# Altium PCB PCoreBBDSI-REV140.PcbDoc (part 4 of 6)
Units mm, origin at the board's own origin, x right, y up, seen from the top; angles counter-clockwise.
Board outline 100 x 72 mm, 6 copper layers (Top Layer, Int1 (GND), Int2 (Sign), Int3 (Sign), Int4 (GND), Bottom Layer), stack 1.551 mm thick; 358 components, 403 nets, 1535 pads, 844 vias.
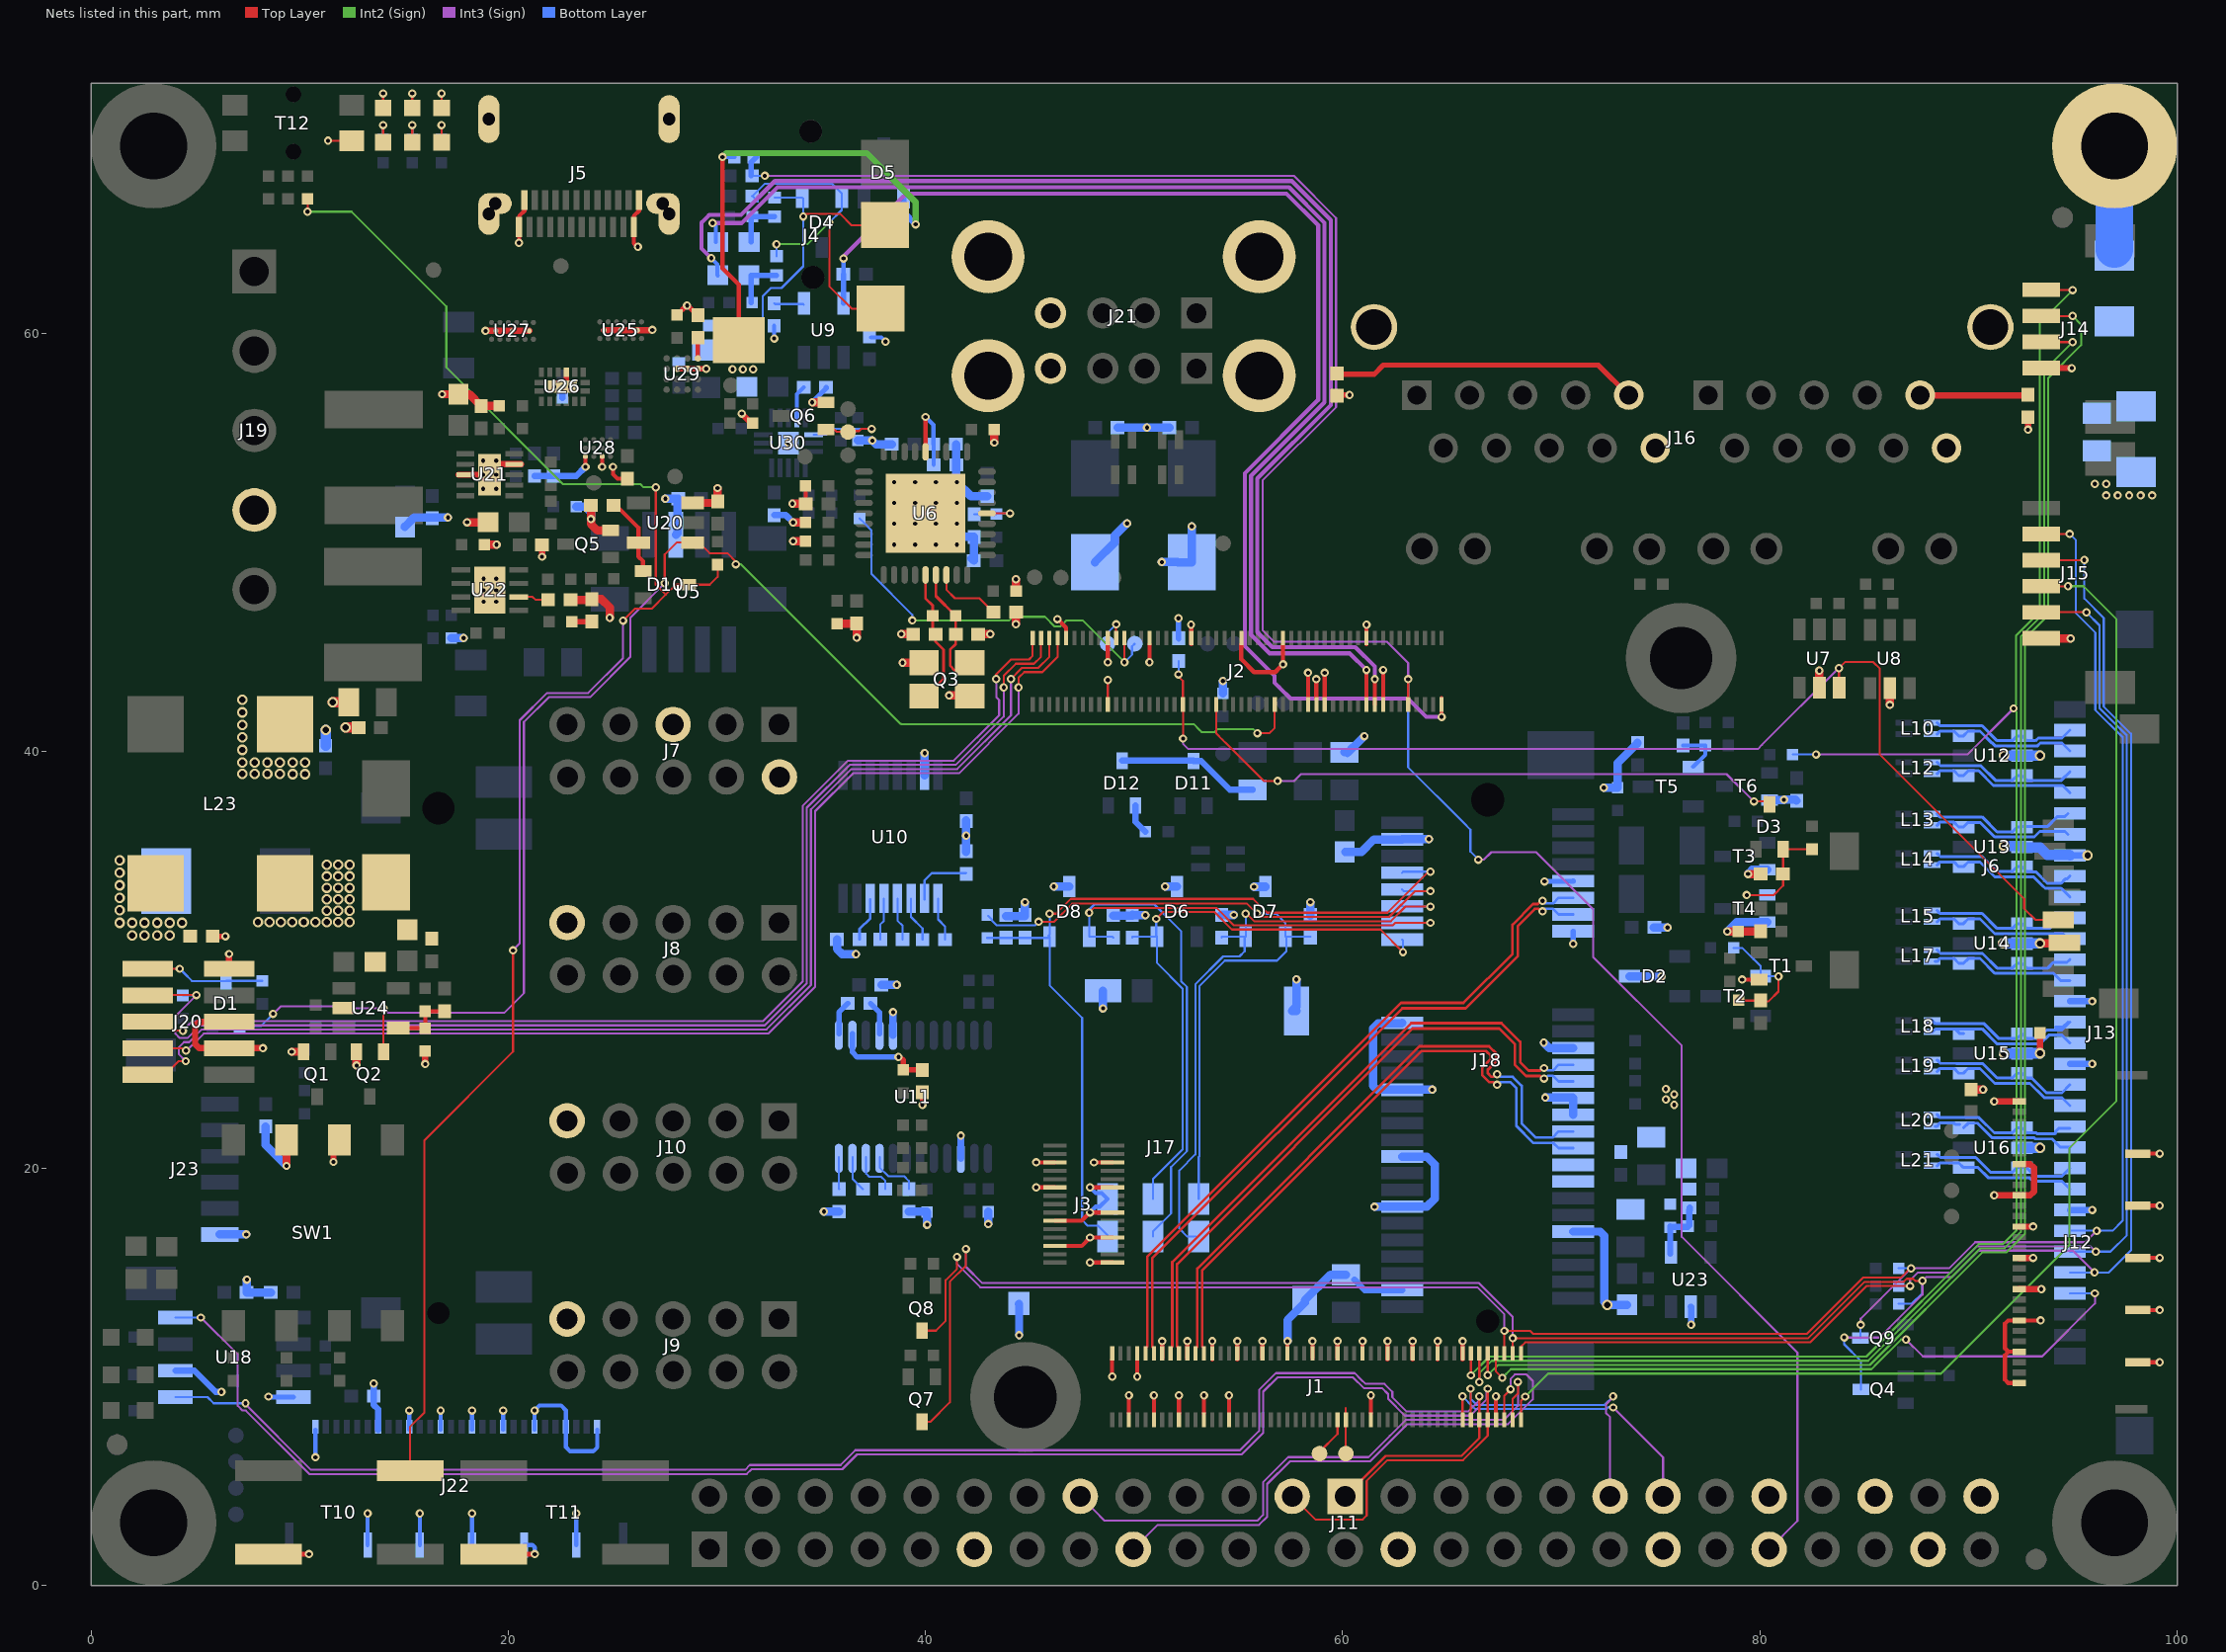
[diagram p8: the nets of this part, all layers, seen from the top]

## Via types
v1: diameter 0.4, hole 0.2, Top Layer to Bottom Layer, tented both sides, 716 vias
v2: diameter 0.5, hole 0.3, Top Layer to Bottom Layer, tented both sides, 102 vias
v3: diameter 0.4, hole 0.2, Top Layer to Bottom Layer, tented bottom, 16 vias
v4: diameter 0.9, hole 0.9, Top Layer to Bottom Layer, 6 vias
v5: diameter 0.5, hole 0.5, Top Layer to Bottom Layer, 2 vias
v6: diameter 3.2, hole 3.2, Top Layer to Bottom Layer, tented both sides, 2 vias

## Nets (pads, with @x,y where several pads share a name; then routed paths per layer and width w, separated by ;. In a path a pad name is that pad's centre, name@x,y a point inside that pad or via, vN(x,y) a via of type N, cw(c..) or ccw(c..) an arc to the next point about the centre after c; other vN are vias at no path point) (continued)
GND: C2.2 C3.1 C4.2 C5.2 C6.1 C7.1 C8.2 C9.1 C10.1 C11.1 C12.1 C13.1 C14.1 C15.1 C16.1 C17.1 C18.1 C19.1 C20.1 C22.1 C23.1 C25.1 C31.1 C32.1 C34.2 C35.2 C37.2 C39.2 C41.2 C42.2 C43.2 C45.1 C46.1 C47.1 C49.1 C50.2 C53.1 C54.1 C55.1 C56.1 C57.1 C58.1 C59.1 C60.1 C61.1 C62.1 C63.1 C64.1 C65.1 C66.1 C69.1 C70.1 C71.1 C72.2 C74.1 C75.1 C76.1 C77.1 C78.1 C79.1 C80.1 C81.1 C82.1 C83.1 C84.1 C86.1 C87.1 C88.1 C90.1 C91.1 C92.1 C97.1 C98.1 C99.1 C100.1 C101.1 C102.2 C103.1 C104.1 C105.1 C106.1 D2.3 D6.3 D7.3 D8.3 D13.1 D14.1 D15.1 J1.8 J1.15 J1.21 J1.27 J1.33 J1.38 J1.39 J1.45 J1.51 J1.57 J1.63 J1.69 J1.72 J1.75 J1.78 J1.81 J1.84 J1.87 J1.90 J1.93 J1.96 J1.99 J2.16 J2.19 J2.30 J2.32 J2.34 J2.39 J2.49 J2.61 J2.71 J2.81 J2.82 J2.91 J3.2 J3.5 J3.8 J3.11 J3.14 J3.19 J3.20 J3.25 J3.26 J5.A1 J5.A12 J5.B1 J5.B12 J6.6 J7.2 J7.5 J8.9 J9.9 J10.9 J11.11 J11.27 J11.37 J11.42 J11.46 J11.47 J11.50 J12.1 J12.4 J12.7 J12.10 J12.13 J12.16 J12.19 J12.22 J12.28 J12.29 J12.30 J12.31 J12.32 J12.33 J13.7 J13.14 J13.17 J13.24 J14.4 J15.6 J16.L10 J16.R10 J17.C5 J17.HD1 J17.HD2DSW1 J17.HD3 J17.HD4 J18.4 J18.9 J18.15 J18.18 J18.21 J18.26 J18.27 J18.29 J18.34 J18.35 J18.37 J18.40 J18.43 J18.50 J20.3 J20.5 J20.9 J21.A4 J21.B4 J22.1 J22.4 J22.7 J22.10 J22.13 J22.16 J22.19 J22.22 J22.28 J22.29 J22.30 J22.31 J22.32 J22.33 J23.6 L23.3 Q1.2 Q2.2 Q3.2 Q3.4 Q5.2 Q6.2 R1.2 R13.1 R14.1 R15.1 R16.1 R17.1 R18.1 R19.1 R22.2 R25.1 R32.1 R36.1 R38.1 R49.1 R60.1 R67.1 R74.1 R77.1 R85.1 R88.1 R90.1 R91.1 R94.2 R96.1 SW1.6 SW1.7 T1.2 T3.2 T4.2 T6.2 T10.3 T11.3 T12.3 U5.6 U6.37 U7.2 U8.2 U10.15 U11.5 U11.15 U12.2 U13.2 U14.2 U15.2 U16.2 U18.2 U18.8 U20.3 U21.3 U21.9 U21.11 U22.9 U23.2 U24.2 U25.B1 U25.B2 U25.B3 U26.11 U26.17 U27.B1 U27.B2 U27.B3 U28.B3 U28.D3 U29.B3 U29.C3 U29.D3 U30.17 | length 282.8
  Top Layer w0.1: v1(11.36,69.25) T12.3@12.5,69.25 ; D15.1@14,70.75 D15.1@14,70.825 v1@14,71.45 ; D13.1@15.4,70.75 D13.1@15.4,70.825 v1@15.4,71.45 ; D14.1@16.8,70.75 D14.1@16.8,70.825 v1@16.8,71.45 ; J2.82@48.738,42.519 v1@48.738,43.398
  Top Layer w0.2: v1(20.51,64.36) 20.52,64.37 20.52,65.64 20.77,65.89 J5.B1@20.77,66.415 ; v1@23.7,53.732 U28.D3@23.7,54.12 ; v1@24.5,53.726 U28.B3@24.5,54.12 ; v1(25.02,53.62) 25.02,53.27 25.24,53.05 C101.1@25.71,53.05 ; v1(26.21,64.17) 26.184,64.17 26.02,64.334 J5.A1@26.02,65.115 26.02,65.64 26.27,65.89 J5.B12@26.27,66.415 ; R17.1@34.25,50.05 R17.1@34.3,50.05 ; R15.1@34.25,52.7 34.26,52.69 C13.1@34.26,51.85 ; R18.1@35.76,46.1 R18.1@35.77,46.11 ; v1(45.31,19.08) 45.314,19.076 J3.19@46.209,19.076 ; v1(45.31,20.28) 45.314,20.276 J3.25@46.209,20.276 ; J3.5@46.209,16.276 47.49,16.276 v1(47.89,16.676) J3.8@48.959,16.676 ; J3.11@46.209,17.476 47.486,17.476 v1(47.89,17.88) 47.894,17.876 J3.14@48.959,17.876 ; v1(46.33,46.32) 46.74,45.91 J2.91@46.74,45.41 ; v1(47.89,19.076) J3.20@48.959,19.076 ; v1@48.074,15.476 J3.2@48.959,15.476 ; v1(48.074,20.276) J3.26@48.959,20.276 ; v1@48.738,43.398 v1(48.74,43.4) ; v1(48.74,44.25) J2.81@48.74,45.19 ; J1.99@48.948,10.839 48.948,9.962 48.95,9.964 v1(48.95,10.01) ; J1.96@49.748,8.229 49.748,9.108 v1(49.75,9.11) ; J1.93@50.148,10.839 50.148,9.962 50.15,9.964 v1(50.15,10.01) ; J2.71@50.738,45.129 50.738,44.252 v1(50.74,44.25) ; J1.90@50.948,8.229 50.948,9.108 v1(50.95,9.11) ; J1.87@51.35,10.9 J1.87@51.35,11.12 v1@51.35,11.71 ; J1.84@52.148,8.229 52.148,9.108 v1(52.15,9.11) ; J1.81@52.55,10.9 J1.81@52.55,11.12 v1(52.55,11.71) ; J2.61@52.738,45.129 v1@52.738,46.05 ; J1.78@53.348,8.229 53.35,8.231 v1(53.35,9.11) ; J1.75@53.748,10.839 53.748,11.712 v1(53.75,11.71) ; J1.72@54.548,8.229 54.55,8.231 v1(54.55,9.11) ; J1.69@54.948,10.839 54.948,11.712 v1(54.95,11.71) ; J2.49@55.138,45.129 55.138,44.392 55.75,43.78 56.768,43.78 56.96,43.972 v1(57.138,44.15) J2.39@57.138,45.129 ; J1.63@56.15,10.9 J1.63@56.15,11.12 v1(56.15,11.71) ; J1.57@57.35,10.9 J1.57@57.35,11.12 v1(57.35,11.71) ; J2.34@58.338,42.519 58.338,42.791 ; 58.34,42.791 v1(58.34,43.75) ; J1.51@58.55,10.9 J1.51@58.55,11.12 v1(58.55,11.71) ; J2.32@58.738,42.519 v1(58.738,43.44) ; J2.30@59.138,42.519 v1(59.138,43.75) ; J1.45@59.75,10.9 J1.45@59.75,11.12 v1(59.75,11.71) ; J1.39@60.95,10.9 v1(60.95,11.71) ; J2.19@61.138,45.129 61.138,46.048 v1(61.14,46.05) ; J1.38@61.348,8.229 61.348,9.108 v1(61.35,9.11) ; v1(61.938,43.88) 61.938,43.608 61.94,43.606 61.94,43.274 61.938,43.272 61.938,42.971 61.94,42.97 61.94,42.791 J2.16@61.94,42.23 ; J1.33@62.148,10.839 62.148,11.712 v1(62.15,11.71) ; J1.27@63.348,10.839 63.348,11.12 63.348,11.712 v1(63.35,11.71) ; J1.21@64.548,10.839 64.548,11.712 v1(64.55,11.71) ; J1.15@65.748,10.839 65.748,11.71 65.748,11.712 v1(65.75,11.71) ; J1.8@67.348,8.229 v1(67.348,9.063) v1@67.348,9.1 ; v1(79.15,29.04) T1.2@79.955,29.04 ; J12.1@92.435,9.7 91.9,9.7 91.75,9.85 91.75,11.04 91.91,11.2 ; J12.4@92.435,11.2 91.91,11.2 ; v1(93.46,12.7) J12.7@92.435,12.7 91.9,12.7 91.75,12.55 91.75,11.36 91.91,11.2 ; J12.29@98.11,10.7 v1(99.165,10.7) ; J12.30@98.11,13.2 v1(99.165,13.2) ; J12.31@98.11,15.7 v1(99.165,15.7) ; J12.32@98.11,18.2 v1(99.165,18.2) ; J12.33@98.11,20.7 v1(99.165,20.7)
  Top Layer w0.25: U26.11@22.79,58.16 22.79,57.66 22.98,57.47 v1(22.98,57.46) ; U29.B3@28.09,58.32 U29.C3@28.59,58.32 U29.D3@29.09,58.32 v1(29.49,58.32)
  Top Layer w0.254: C70.1@5.83,31.12 5.84,31.11 v1@6.44,31.11 ; T10.3@8.5,1.5 v1(10.45,1.5) ; T11.3@19.3,1.5 v1(21.27,1.5) ; R91.1@28.09,60.9 28.545,61.355 v1(28.57,61.355) ; v1@28.57,61.35 28.6,61.35 29.06,60.89 C102.2@29.09,60.89 ; v1(39.85,23.04) C41.2@39.85,23.63 ; Q3.4@42.121,42.634 Q3.4@42.125,42.63 ; C54.1@59.73,57.06 v1(60.33,57.06)
  Top Layer w0.3: v1(91.23,18.7) J12.19@92.435,18.7 92.96,18.7 93.14,18.88 93.14,20.02 92.96,20.2 J12.22@92.435,20.2 ; v1(91.23,23.2) J12.28@92.435,23.2 ; J12.10@92.435,14.2 93.027,14.2 v1(93.49,14.2) ; J12.13@92.435,15.7 92.74,15.7 v1(93.09,15.7) ; J12.16@92.435,17.2 92.74,17.2 v1(93.09,17.2) ; R25.1@93.42,26.48 93.425,26.475 93.425,25.515 v2(93.43,25.51)
  Top Layer w0.305: J20.5@6.62,27.02 5.17,27.02 4.99,26.84 4.99,25.95 5.19,25.75 J20.3@6.62,25.75 v1(8.24,25.75) ; J20.9@6.62,29.56 v1(6.62,30.27) ; v1(11.62,20.3) 11.62,21.06 SW1.6@11.91,21.35 ; v1(16.02,24.99) R88.1@16.02,25.61 ; U21.3@17.615,53.24 U21.3@17.94,53.24 v1(18.8,53.24) U21.11@19.11,53.24 19.61,53.74 U21.9@20.28,53.74 U21.9@20.605,53.74 ; v1(18.91,60.137) U27.B1@19.402,60.137 U27.B2@20.202,60.137 U27.B3@21.002,60.137 ; v1(21.62,49.31) C80.1@21.62,49.88 C80.1@21.642,49.88 ; U25.B1@24.59,60.17 U25.B2@25.39,60.17 U25.B3@26.19,60.17 26.9,60.17 v1(26.91,60.18) ; v1(31.19,56.17) 31.645,55.715 R90.1@31.72,55.715 ; U7.2@82.85,43.03 U7.2@82.865,43.045 ; v1(92.85,55.4) C53.1@92.85,56 C53.1@92.85,56.04 ; J14.4@93.59,58.355 94.945,58.355 v1(94.95,58.35) ; v1@94.885,45.395 v1(94.89,45.39)
  Top Layer w0.35: C83.1@12.36,42.33 C83.1@12.59,42.33
  Top Layer w0.4: v1(9.37,20.11) SW1.7@9.37,21.35 ; v1(9.62,25.58) 10.06,25.58 10.19,25.45 Q1.2@10.19,25.575 ; Q2.2@12.72,25.46 Q2.2@12.72,25.585 12.72,24.98 12.73,24.97 v1(12.73,24.92) ; v1(16.83,57.1) C75.1@17.614,57.1 18.144,57.1 C76.1@18.704,56.54 R67.1@19.574,56.54 ; v1(18.03,50.96) C79.1@18.93,50.96 ; R74.1@18.86,49.89 v1(19.44,49.89) ; C81.1@22.99,47.24 C84.1@24.01,47.24 ; C74.1@23.96,51.78 v1(23.96,51.11) 23.96,50.88 24.27,50.57 Q5.2@24.905,50.57 ; C84.1@24.01,47.28 24.47,47.28 24.86,46.89 v1(24.86,46.38) ; U20.3@28.84,51.89 29.96,51.89 C69.1@30.04,51.97 30.01,52 30.03,52.02 v1(30.03,52.6) ; v1(33.62,51.85) C13.1@34.26,51.85 ; v1(33.66,50.05) R17.1@34.25,50.05 ; v1(33.66,50.95) R16.1@34.25,50.95 ; v1(34.57,56.71) Q6.2@35.225,56.71 ; R18.1@35.77,46.11 C10.1@36.7,46.11 v1(36.7,45.43) ; v1(38.84,45.6) C18.1@39.41,45.6 ; v1(38.901,44.234) Q3.2@39.921,44.234 ; v1(41.13,42.66) 42.095,42.66 Q3.4@42.121,42.634 ; C17.1@42.55,45.58 C17.1@42.53,45.6 v1(43.1,45.6) ; v1(43.3,54.78) R14.1@43.3,55.41 ; C16.1@44.266,46.576 C16.1@44.34,46.65 ; v1@44.34,46.11 C16.1@44.34,46.65 ; v1(44.34,48.23) 44.34,47.68 R13.1@44.35,47.67 ; C16.1@44.35,46.64 C16.1@44.34,46.65 ; v1(78.44,31.35) R19.1@78.96,31.35 80.02,31.35 C19.1@80.03,31.36 ; v1(79.43,34.1) C25.1@80.03,34.1 ; U7.2@82.85,43.03 v1(82.85,43.85) ; v1(86.231,42.209) U8.2@86.23,43.01 ; C46.1@90.12,23.77 v1(90.695,23.77) ; v2@93.43,30.78 94.58,30.78 J6.6@94.6,30.8 ; J15.6@93.59,45.395 v1@94.885,45.395
  Top Layer w0.406: v1(18.82,47.7) 18.83,47.71 U22.9@19.11,47.71 ; U6.37@40,51.39 U6.37@40,51.4
  Top Layer w0.5: v2(11.59,42.33) C83.1@12.36,42.33 ; v2(12.2,41.12) C82.1@12.82,41.12
  Int3 (Sign) w0.1: v1(61.35,9.11) v1@61.45,9.01
  Bottom Layer w0.2: v1(10.76,6.14) J22.28@10.76,7.46 ; v1@13.25,3.45 13.26,3.44 J22.33@13.26,1.935 ; J22.19@15.26,7.46 J22.19@15.26,7.61 v1(15.26,8.385) ; J22.32@15.76,1.935 v1@15.76,3.44 ; J22.16@16.76,7.46 J22.16@16.76,7.61 v1(16.76,8.385) ; J22.31@18.26,1.935 v1@18.26,3.44 ; J22.13@18.26,7.46 J22.13@18.26,7.61 v1(18.26,8.385) ; J22.10@19.76,7.46 v1(19.76,8.385) ; J22.30@20.76,1.935 21.155,1.935 21.27,1.82 v1(21.27,1.5) ; J22.7@21.26,7.46 v1@21.26,8.33 ; v1(21.26,8.385) 21.495,8.62 22.53,8.62 22.76,8.39 J22.4@22.76,7.61 22.76,6.63 22.96,6.43 24.07,6.43 24.26,6.62 J22.1@24.26,7.46 ; J22.29@23.26,1.935 v1@23.26,3.44 ; v1(32.75,59.77) C32.1@32.75,60.38 ; C31.1@37.4,59.82 37.88,59.82 v1(38.08,59.62) ; v1(47.89,17.88) 48.164,18.154 48.354,18.154 J17.C5@48.72,18.52 48.438,18.802 48.164,18.802 v1(47.89,19.076) ; v1@57.113,44.125 v1(57.138,44.15) ; C64.1@60.225,39.805 60.51,40.09 60.51,40.185 C64.1@60.51,40.31
  Bottom Layer w0.25: v1(34.57,56.71) 35.24,57.38 C103.1@35.24,57.43
  Bottom Layer w0.254: v1(8.51,9.052) 8.537,9.025 U18.8@9.695,9.025 ; v1(52.13,46.36) C20.1@52.13,45.4 52.13,45.375 C20.1@52.137,45.367 ; v1(69.676,33.746) 69.683,33.753 71.043,33.753 J18.9@71.05,33.76 ; v1(71.05,30.75) J18.15@71.05,31.36
  Bottom Layer w0.3: v1(13.55,9.68) C106.1@13.55,9.07 13.55,8.65 13.76,8.44 J22.22@13.76,7.61 J22.22@13.76,7.46
  Bottom Layer w0.305: U18.2@4.045,10.295 4.955,10.295 5.97,9.28 v1(6.25,9.28) ; C98.1@21.26,53.18 C97.1@22.17,53.18 23.26,53.18 v1(23.7,53.62) ; v1(22.2,57.46) 22.48,57.46 22.59,57.35 R96.1@22.59,56.92 ; C105.1@32.75,51.3 33.31,51.3 v1(33.66,50.95) ; C63.1@60.552,14.66 61.052,14.16 J18.50@62.85,14.16 ; U23.2@76.68,13.36 76.7,13.34 v1(76.7,12.5) ; J13.24@94.86,18 v1(95.93,18) ; J13.17@94.86,25 v1(95.93,25) ; J13.14@94.86,28 v1(95.93,28) ; J13.7@94.86,35 v2(95.71,35)
  Bottom Layer w0.35: U11.5@38.445,26.37 v1(38.445,27.48) ; U11.15@41.695,20.47 v1(41.695,21.56)
  Bottom Layer w0.4: J23.6@6.17,16.825 7.435,16.825 v1(7.44,16.82) ; v1(7.47,14.66) 7.46,14.65 C50.2@7.46,14.04 C49.1@8.62,14.04 ; C47.1@8.37,22 8.37,21.11 v1(9.37,20.11) ; C77.1@15.05,50.73 15.05,50.755 15.485,51.19 v1(17.11,51.19) ; R77.1@17.27,45.41 v1(17.86,45.41) ; R60.1@23.26,51.71 23.7,51.71 23.96,51.45 v1(23.96,51.11) ; v1(27.53,52.09) C3.1@28.15,52.09 28.15,52.04 28.118,52.008 28.118,51.333 U5.6@28.15,51.3 ; U5.6@28.035,50.36 28.118,50.443 U5.6@28.118,51.3 ; v1(35.13,17.92) C42.2@35.86,17.92 ; C37.2@35.76,30.97 35.76,30.51 36.01,30.26 v1(36.67,30.26) ; R94.2@36.75,54.88 v1(37.45,54.88) 37.63,54.7 C12.1@38.39,54.7 ; C39.2@37.89,28.79 v1(38.62,28.79) ; C43.2@39.2,17.92 40.06,17.92 R38.1@40.08,17.9 v1(40.08,17.29) ; U10.15@39.955,38.83 39.96,38.835 v1(39.96,39.9) ; C14.1@41.46,54.7 41.465,54.695 C15.1@41.465,53.729 ; C15.1@41.473,53.721 41.465,53.713 41.465,52.925 v3(41.5,52.89) 42.18,52.21 C11.1@42.96,52.21 ; v3(41.5,50.89) 41.5,50.65 41.89,50.26 C8.2@42.33,50.26 42.33,49.13 C9.1@42.32,49.12 C9.1@42.21,49.23 ; C35.2@41.95,35.15 C35.2@41.95,35.19 v1(41.95,35.94) C34.2@41.95,36.64 C34.2@41.95,36.68 ; v1(43.01,17.32) R36.1@43.01,17.91 ; J17.HD4@44.48,13.5 44.49,13.49 v1(44.49,11.99) ; C4.2@48.12,49.04 49.07,49.99 49.07,50.32 v1(49.66,50.91) ; C6.1@49.21,55.5 v1(50.62,55.5) C7.1@51.69,55.5 ; v1(51.33,49.05) 52.084,49.05 52.094,49.04 C5.2@52.764,49.04 52.77,49.046 v1(52.77,50.77) ; R22.2@54.26,42.76 v1(54.26,43.35) ; v1(57.35,11.71) 57.35,12.72 58.18,13.55 J17.HD1@58.18,13.66 59.41,14.89 C63.1@60.16,14.89 ; C64.1@60.09,39.94 60.265,39.94 60.51,40.185 60.565,40.24 v1@61.035,40.71 ; C65.1@60.12,35.16 60.9,35.16 61.5,35.76 J18.4@62.85,35.76 62.86,35.77 v1(64.13,35.77) ; v1(61.53,18.15) 61.536,18.156 62.847,18.156 J18.40@62.85,18.16 64.04,18.16 64.41,18.53 64.41,20.18 64.034,20.556 62.854,20.556 J18.34@62.85,20.56 ; J18.18@62.85,26.96 62.84,26.95 61.7,26.95 61.45,26.7 61.45,23.95 61.64,23.76 J18.26@62.85,23.76 v1(64.29,23.76) ; v1(69.64,26.02) 69.9,25.76 J18.21@71.05,25.76 ; v1(69.71,23.38) 71.03,23.38 J18.27@71.05,23.36 J18.29@71.05,22.56 ; J18.43@71.05,16.96 72.34,16.96 72.55,16.75 72.55,13.58 v2(72.68,13.45) C88.1@73.63,13.45 ; v1(72.52,38.24) R49.1@73.17,38.24 73.17,39.414 74.016,40.26 74.02,40.26 74.13,40.37 C23.1@74.13,40.39 ; D2.3@73.75,29.2 v1(75.28,29.2) ; C45.1@74.9,31.54 C45.1@74.94,31.54 v1(75.57,31.54) ; v1(78.44,31.35) 78.88,31.79 T4.2@80.355,31.79 ; v1(79.43,34.1) 79.63,34.3 T3.2@80.355,34.3 ; T6.2@80.455,37.65 81.14,37.65 v1(81.15,37.66) 81.71,37.66 C22.1@81.76,37.61
  Bottom Layer w0.406: C60.1@43.86,32.09 44.77,32.09 C59.1@44.77,32.13 v1(44.77,32.75) ; v1(46.15,33.5) D8.3@46.9,33.5 ; v1(48.51,27.66) J17.HD3@48.51,28.51 ; C56.1@49,32.1 49.92,32.1 C55.1@49.92,32.14 49.93,32.13 v1(50.54,32.13) ; v1(51.49,33.5) D6.3@52.05,33.5 ; C57.1@54.2,32.1 C57.1@54.2,32.14 v1(54.78,32.14) ; v1(55.75,33.49) 56.29,33.49 D7.3@56.3,33.5 ; J17.HD2DSW1@57.78,27.535 57.569,27.535 57.78,27.746 v1(57.78,29.05) ; C58.1@58.45,32.1 C58.1@58.45,32.14 v1(58.45,32.75)
  Bottom Layer w0.5: C71.1@11.25,40.25 v2(11.25,41.002) ; v2(91.658,30.77) U14.2@92.56,30.77 v2(93.43,30.77) ; v2(91.69,25.5) U15.2@92.56,25.5 92.57,25.51 v2(93.43,25.51) ; v2(91.69,35.452) 91.692,35.45 92.51,35.45 U13.2@92.56,35.4 92.583,35.377 93.423,35.377 93.775,35.025 94.835,35.025 J13.7@94.86,35 ; v2(91.69,39.77) U12.2@92.56,39.77 92.563,39.773 v2(93.433,39.773) ; U16.2@92.56,20.98 v2(93.42,20.98)
  other v1: 13.26,3.45 15.76,3.45 18.26,3.45 23.26,3.45 51.35,11.71 47.89,15.476 75.89,23.04 75.49,23.29 75.89,23.54 75.49,23.79 6.44,31.12 61.04,40.71 52.73,46.05 44.34,46.08 18.82,47.15 19.42,47.15 19.42,47.7 18.82,48.25 19.42,48.25 96.6,52.25 97.15,52.25 97.7,52.25 98.25,52.25 98.8,52.25 18.8,52.56 19.42,52.56 96.05,52.8 96.6,52.8 19.42,53.24 24.5,53.62 18.8,53.92 19.42,53.92 33.43,54.76 30.75,58.3 31.25,58.3 31.74,58.3 14,71.52 15.4,71.52 16.8,71.52
  other v2: 8,31.79 8.55,31.79 9.099,31.79 9.649,31.79 10.199,31.79 10.75,31.79 11.3,31.79 11.85,31.79 12.4,31.79 11.3,32.34 11.85,32.34 12.4,32.34 11.3,32.89 11.85,32.89 12.4,32.89 11.3,33.44 11.85,33.44 12.4,33.44 11.3,33.99 11.85,33.99 12.4,33.99 11.3,34.54 11.85,34.54 12.4,34.54
  other v3: 38.5,49.89 39.5,49.89 40.5,49.89 41.5,49.89 38.5,50.89 39.5,50.89 40.5,50.89 38.5,51.89 39.5,51.89 40.5,51.89 41.5,51.89 38.5,52.89 39.5,52.89 40.5,52.89
GND_SHIELD: C1.1 C2.1 J5.SH1 J5.SH2 J5.SH3 J5.SH4 J16.L15 J16.R15 J21.9 J21.10 J21.11 J21.12 R1.1
GNDIN: J19.4 L23.4
  other v2: 9.665,38.89 10.265,38.89 7.25,38.9 7.85,38.9 8.45,38.9 9.05,38.9 7.25,39.45 7.85,39.45 8.45,39.45 9.05,39.45 9.665,39.44 10.265,39.44 7.25,40.05 7.25,40.65 7.25,41.25 7.25,41.85 7.25,42.45
GPIO_J1_44: J1.44 TP30.1 | length 2.2
  Top Layer w0.1: TP30.1@60.15,6.32 J1.44@60.15,7.94 60.15,8.231 60.15,8.501
GPIO_J1_46: J1.46 TP31.1 | length 2
  Top Layer w0.1: TP31.1@58.89,6.32 58.89,6.4 59.75,7.26 J1.46@59.75,7.94
I2C_B_SCL: J1.3 J13.27 J15.3 Q4.3 Q7.3 R8.2 | length 118.7
  Top Layer w0.1: Q7.3@39.83,7.845 40.235,7.845 41.17,8.78 41.17,14.55 41.934,15.314 v1(41.934,16.13) ; J1.3@68.15,11.12 68.15,11.73 68.27,11.85 82.317,11.85 85.017,14.55 86.89,14.55 87.04,14.7 87.345,14.7 87.445,14.6 v1(87.79,14.6) ; J15.3@93.595,49.15 v1(95.55,49.15)
  Int3 (Sign) w0.1: v1(41.934,16.13) 41.934,15.276 42.72,14.49 66.537,14.49 68.15,12.877 v1(68.15,11.85) ; v1(84.04,11.89) 84.047,11.883 85.738,11.883 86.21,12.355 86.21,12.36 87.79,13.94 v1(87.79,14.6) 87.98,14.79 89.223,14.79 90.483,16.05 95,16.05 v1(96.04,15.01)
  Bottom Layer w0.1: v1(84.04,11.89) 84.04,11.56 84.835,10.765 Q4.3@84.835,9.39 ; R8.2@86.65,13.5 87.28,13.5 87.79,14.01 v1(87.79,14.6) ; J13.27@94.86,15 96.04,15 96.73,15 97.79,16.06 97.79,40.82 96.48,42.13 96.48,46.37 95.55,47.3 v1(95.55,49.15)
I2C_B_SDA: J1.5 J13.25 J15.2 Q8.3 Q9.3 R9.2 | length 107.8
  Top Layer w0.1: Q8.3@39.83,12.215 40.505,12.215 40.97,12.68 40.97,14.633 41.51,15.173 v1(41.51,15.75) ; J1.5@67.75,10.841 v1(67.75,12.2) 68.005,12.2 68.295,12.2 68.99,12.2 69.14,12.05 82.234,12.05 84.934,14.75 86.75,14.75 87.2,15.2 v1(87.25,15.2) ; J15.2@93.59,50.395 93.595,50.4 v1(94.85,50.4)
  Int3 (Sign) w0.1: v1(41.51,15.75) 41.51,15.41 42.63,14.29 66.454,14.29 67.75,12.994 v1(67.75,12.2) ; v1(84.83,12.49) 84.83,12.78 v1(87.25,15.2) 89.067,15.2 90.317,16.45 95.59,16.45 v1(96.14,17)
  Bottom Layer w0.1: Q9.3@84.825,11.85 84.825,12.485 v1(84.83,12.49) ; R9.2@86.65,15.2 v1(87.25,15.2) ; v1(94.85,50.4) 95.15,50.1 95.15,46.6 96.08,45.67 96.08,41.964 97.39,40.654 97.39,17.49 96.9,17 v1(96.14,17) J13.25@94.86,17
I2S_B_RXC: J2.79 TP28.1 | length 1.8
  Top Layer w0.1: J2.79@49.14,45.41 v1(49.14,46.07)
  Bottom Layer w0.1: TP28.1@48.73,45.14 48.738,45.148 48.738,45.668 v1(49.14,46.07)
I2S_B_RXFS: J2.77 R102.2 TP27.1 | length 19.6
  Top Layer w0.1: v1@49.54,44.24 v1(49.54,44.25) J2.77@49.54,45.41
  Int2 (Sign) w0.1: v1(39.37,46.26) 44.025,46.26 44.195,46.43 45.725,46.43 46.185,45.97 46.475,45.97 46.765,46.26 47.53,46.26 v1(49.54,44.25)
  Bottom Layer w0.1: R102.2@36.84,51.15 37.065,50.925 37.41,50.58 37.41,48.491 39.37,46.531 v1(39.37,46.26) ; v1(49.54,44.25) 49.902,44.612 49.902,45.012 TP27.1@50.03,45.14
I\2\C\_\B\_\I\R\Q\: J1.1 J13.26 J15.5 R5.2 | length 66.7
  Top Layer w0.1: J1.1@68.55,10.841 68.55,11.45 68.75,11.65 82.4,11.65 85.1,14.35 v1(87.2,14.35) ; J15.5@93.59,46.645 93.595,46.65 v1(95.65,46.65)
  Int3 (Sign) w0.1: v1(87.2,14.35) 87.2,14.626 87.574,15 89.15,15 90.4,16.25 95.848,16.25 96.098,16 v1(96.1,16)
  Bottom Layer w0.1: R5.2@86.65,14.35 v1(87.2,14.35) ; J13.26@94.86,16 v1(96.1,16) 96.8,16 97.59,16.79 97.59,40.737 96.28,42.047 96.28,46.02 v1(95.65,46.65)
ILIM_5V_VBUS: Q6.1 TP8.1 U30.6 | length 5.2
  Top Layer w0.1: Q6.1@35.225,55.41 35.633,55.41 35.74,55.303 36.277,55.303 TP8.1@36.29,55.29 36.338,55.338 36.818,55.338 36.92,55.44 v1(37.42,55.44)
  Bottom Layer w0.1: U30.6@34.63,55.16 35.23,55.16 35.52,55.45 37.41,55.45 v1(37.42,55.44)
JTAG_TCK: J2.93 J20.4 | length 58
  Top Layer w0.1: J20.4@2.72,25.75 4.368,25.75 4.478,25.64 v1(4.55,25.64) ; v1(44.46,43.05) 44.46,43.51 44.73,43.78 45.6,43.78 46.338,44.518 46.338,44.849 J2.93@46.338,45.129
  Int3 (Sign) w0.1: v1(4.55,25.64) 4.59,25.64 5.4,26.45 32.463,26.45 34.71,28.697 34.71,37.111 36.531,38.932 41.606,38.932 44.46,41.786 v1(44.46,43.05)
JTAG_TDI: J2.97 J20.8 R7.1 | length 61.1
  Top Layer w0.1: J20.8@2.72,28.29 2.73,28.3 v1(5.05,28.3) ; v1(43.75,43.05) 43.75,43.305 43.75,43.6 44.33,44.18 44.53,44.18 ; 44.53,44.18 45.2,44.18 45.538,44.518 45.538,44.849 J2.97@45.538,45.129
  Int3 (Sign) w0.1: v1(5.05,28.3) 4.05,27.3 4.05,26.445 4.255,26.24 4.624,26.24 5.234,26.85 32.297,26.85 34.31,28.863 34.31,37.277 36.365,39.332 41.44,39.332 43.75,41.642 v1(43.75,43.05)
  Bottom Layer w0.1: R7.1@4.4,28.28 5.03,28.28 v1(5.05,28.3)
JTAG_TDO: J2.99 J20.6 | length 56.9
  Top Layer w0.1: J20.6@2.72,27.02 3.05,26.69 3.89,26.69 3.99,26.59 v1(4.4,26.59) ; v1@43.39,43.44 43.39,43.67 44.1,44.38 44.481,44.38 44.96,44.38 45.138,44.558 45.138,44.849 J2.99@45.138,45.129
  Int3 (Sign) w0.1: v1(4.4,26.59) 4.86,27.05 32.214,27.05 34.11,28.945 34.11,37.36 36.282,39.532 41.357,39.532 43.53,41.705 43.53,42.443 43.4,42.573 43.4,43.45 v1@43.39,43.44
  other v1: 43.39,43.45
JTAG_TMS: J2.95 J20.2 | length 58.9
  Top Layer w0.1: J20.2@2.72,24.48 3.54,24.48 4.19,25.13 v1(4.54,25.13) ; v1(44.1,43.45) 44.58,43.93 44.63,43.98 45.4,43.98 45.938,44.518 45.938,44.849 J2.95@45.938,45.129
  Int3 (Sign) w0.1: v1(4.54,25.13) 4.2,25.47 4.2,25.785 4.455,26.04 4.707,26.04 5.317,26.65 32.38,26.65 34.51,28.78 34.51,37.194 36.448,39.132 41.523,39.132 44.1,41.709 v1(44.1,43.45)
LACLK_N: J13.8 L14.3 U13.3 | length 7.3
  Bottom Layer w0.141: L14.3@88.495,35.085 88.65,34.93 89.164,34.93 90.356,34.929 ; 90.356,34.93 90.66,34.93 91.37,34.22 92.105,34.22 92.335,34.45 U13.3@92.56,34.45 92.789,34.221 93.059,34.221 93.073,34.207 93.222,34.207 93.769,33.66 94.439,33.66 94.64,33.861 94.721,33.861 J13.8@94.86,34
LACLK_P: J13.9 L14.2 U13.4 | length 7.3
  Bottom Layer w0.141: L14.2@88.495,34.535 88.574,34.614 88.574,34.638 88.62,34.683 89.302,34.683 89.535,34.45 U13.4@89.76,34.45 89.986,34.676 90.555,34.676 91.265,33.966 93.122,33.966 93.403,33.685 93.559,33.53 93.669,33.419 94.441,33.419 J13.9@94.86,33
LADATA0_N: J13.1 L10.3 U12.1 | length 7.1
  Bottom Layer w0.141: L10.3@88.495,41.355 88.574,41.276 88.574,41.252 88.62,41.206 90.654,41.206 91.37,40.49 92.105,40.49 92.335,40.72 U12.1@92.56,40.72 92.789,40.491 U12.1@93.059,40.491 ; U12.1@93.06,40.49 93.21,40.49 93.34,40.62 94.48,40.62 J13.1@94.86,41
LADATA0_P: J13.2 L10.2 U12.6 | length 7.1
  Bottom Layer w0.141: L10.2@88.495,40.805 88.574,40.884 88.574,40.908 88.62,40.953 89.302,40.953 89.535,40.72 U12.6@89.76,40.72 89.986,40.946 90.555,40.946 91.111,40.39 91.129,40.39 91.27,40.249 92.205,40.249 ; 92.205,40.249 92.96,40.249 ; 92.96,40.249 93.31,40.249 93.44,40.379 94.481,40.379 J13.2@94.86,40
LADATA1_N: J13.3 L12.3 U12.3 | length 7.1
  Bottom Layer w0.141: L12.3@88.495,39.455 88.656,39.294 89.402,39.294 89.405,39.291 90.157,39.291 90.16,39.294 90.586,39.294 91.29,38.59 92.105,38.59 92.335,38.82 U12.3@92.56,38.82 92.789,38.591 U12.3@93.059,38.591 ; U12.3@93.06,38.59 94.45,38.59 J13.3@94.86,39
LADATA1_P: J13.4 L12.2 U12.4 | length 7.1
  Bottom Layer w0.141: L12.2@88.495,38.905 88.574,38.984 88.574,39.008 88.62,39.053 89.302,39.053 89.535,38.82 U12.4@89.76,38.82 89.989,39.049 90.257,39.049 90.26,39.052 90.487,39.052 91.19,38.349 91.27,38.349 92.205,38.349 ; 92.205,38.349 92.96,38.349 93.9,38.349 94.511,38.349 J13.4@94.86,38
LADATA2_N: J13.5 L13.3 U13.1 | length 7
  Bottom Layer w0.141: L13.3@88.495,36.985 88.574,36.906 88.574,36.882 88.62,36.836 90.654,36.836 91.37,36.12 92.105,36.12 92.335,36.35 U13.1@92.56,36.35 92.6,36.39 93.8,36.39 94.271,36.861 94.621,36.861 J13.5@94.76,37
LADATA2_P: J13.6 L13.2 U13.6 | length 7
  Bottom Layer w0.141: L13.2@88.495,36.435 88.574,36.514 88.574,36.538 88.62,36.583 89.302,36.583 89.535,36.35 U13.6@89.76,36.35 89.986,36.576 90.555,36.576 91.252,35.879 93.159,35.879 93.419,36.139 94.621,36.139 J13.6@94.76,36
LADATA3_N: J13.10 L15.3 U14.1 | length 7.1
  Bottom Layer w0.141: L15.3@88.495,32.355 88.574,32.276 88.574,32.252 88.62,32.206 90.654,32.206 91.37,31.49 92.105,31.49 92.335,31.72 U14.1@92.56,31.72 92.789,31.491 U14.1@93.059,31.491 ; U14.1@93.06,31.49 93.89,31.49 94.261,31.861 94.821,31.861 J13.10@94.86,31.9
LADATA3_P: J13.11 L15.2 U14.6 | length 7.1
  Bottom Layer w0.141: L15.2@88.495,31.805 88.574,31.884 88.574,31.908 88.62,31.953 89.302,31.953 89.535,31.72 U14.6@89.76,31.72 89.986,31.946 90.555,31.946 91.261,31.24 91.964,31.24 ; 91.964,31.241 93.156,31.241 ; 93.156,31.24 94.52,31.24 J13.11@94.86,30.9
LBCLK_N: J13.20 L20.3 U16.1 | length 7.1
  Bottom Layer w0.141: L20.3@88.495,22.565 88.574,22.486 88.574,22.465 88.62,22.42 90.499,22.42 90.519,22.4 90.531,22.4 91.231,21.7 92.105,21.7 92.335,21.93 U16.1@92.56,21.93 92.79,21.7 93.247,21.7 93.305,21.642 94.135,21.642 94.181,21.687 94.181,21.771 94.31,21.9 J13.20@94.86,21.9
LBCLK_P: J13.21 L20.2 U16.6 | length 7
  Bottom Layer w0.141: L20.2@88.395,22.015 88.495,22.015 88.574,22.094 88.574,22.114 88.62,22.16 89.305,22.16 89.355,22.11 U16.6@89.58,22.11 ; U16.6@89.76,21.93 89.989,22.159 90.431,22.159 91.139,21.451 93.156,21.451 93.206,21.401 94.01,21.401 94.41,21 J13.21@94.86,21
LBDATA0_N: J13.12 L17.3 U14.3 | length 7.1
  Bottom Layer w0.141: L17.3@88.495,30.455 88.656,30.294 89.402,30.294 89.405,30.291 90.157,30.291 90.16,30.294 90.648,30.294 90.652,30.29 90.67,30.29 91.37,29.59 92.105,29.59 92.335,29.82 U14.3@92.56,29.82 92.789,29.591 U14.3@93.059,29.591 ; U14.3@93.06,29.59 93.8,29.59 94.071,29.861 94.721,29.861 J13.12@94.86,30
LBDATA0_P: J13.13 L17.2 U14.4 | length 7.2
  Bottom Layer w0.141: L17.2@88.395,29.905 88.495,29.905 88.574,29.984 88.574,30.008 88.62,30.053 89.302,30.053 89.535,29.82 U14.4@89.76,29.82 89.989,30.049 90.257,30.049 90.26,30.053 90.548,30.053 91.252,29.349 94.061,29.349 94.41,29 J13.13@94.86,29
LBDATA1_N: J13.15 L18.3 U15.1 | length 8.2
  Bottom Layer w0.141: L18.3@88.245,27.085 88.41,26.92 89.164,26.92 90.356,26.921 90.751,26.921 91.46,26.212 92.06,26.212 92.069,26.221 92.331,26.221 U15.1@92.56,26.45 92.79,26.22 93.35,26.22 93.75,26.62 94.48,26.62 J13.15@94.86,27 ; J13.15@94.179,26.771 94.531,26.771 J13.15@94.76,27
LBDATA1_P: J13.16 L18.2 U15.6 | length 7.8
  Bottom Layer w0.141: L18.2@88.245,26.535 88.275,26.535 88.413,26.673 U15.6@89.358,26.673 ; U15.6@89.76,26.45 89.588,26.45 89.358,26.679 89.537,26.679 90.651,26.679 91.36,25.971 93.441,25.971 93.449,25.979 ; 93.45,25.979 93.85,26.379 94.481,26.379 J13.16@94.86,26
LBDATA2_N: J13.18 L19.3 U15.3 | length 7.4
  Bottom Layer w0.141: L19.3@88.495,25.185 88.656,25.024 89.402,25.024 89.405,25.021 90.356,25.021 ; 90.356,25.02 90.67,25.02 91.37,24.32 92.105,24.32 92.335,24.55 U15.3@92.56,24.55 92.789,24.321 93.029,24.321 93.73,23.62 94.48,23.62 J13.18@94.86,24
LBDATA2_P: J13.19 L19.2 U15.4 | length 7.4
  Bottom Layer w0.141: L19.2@88.495,24.635 88.574,24.714 88.574,24.738 88.62,24.783 89.302,24.783 89.535,24.55 U15.4@89.76,24.55 89.986,24.776 90.555,24.776 91.265,24.066 92.943,24.066 93.589,23.42 93.63,23.379 94.481,23.379 J13.19@94.86,23
LBDATA3_N: J13.22 L21.3 U16.3 | length 7.1
  Bottom Layer w0.141: L21.3@88.495,20.665 88.65,20.51 89.164,20.51 ; 89.164,20.509 90.347,20.509 91.046,19.81 92.115,19.81 92.335,20.03 U16.3@92.56,20.03 92.78,20.03 93.19,19.62 94.48,19.62 J13.22@94.86,20
LBDATA3_P: J13.23 L21.2 U16.4 | length 7
  Bottom Layer w0.141: L21.2@88.495,20.115 88.574,20.194 88.574,20.211 88.62,20.256 89.534,20.256 U16.4@89.76,20.03 90.46,20.03 90.94,19.55 92.91,19.55 93.081,19.379 94.48,19.379 94.481,19.379 J13.23@94.86,19
MPCIE_CLK_N: J1.91 J18.11 | length 32.9
  Top Layer w0.127: J1.91@50.548,11.368 50.642,11.462 50.642,15.772 62.797,27.927 65.788,27.927 68.139,30.278 68.139,31.675 69.122,32.658 69.354,32.658 69.506,32.81 v1(69.58,32.81)
  Bottom Layer w0.127: v1(69.58,32.81) 69.7,32.69 69.918,32.69 70.08,32.69 70.35,32.96 J18.11@71.05,32.96
MPCIE_CLK_P: J1.89 J18.13 | length 32.5
  Top Layer w0.127: J1.89@50.948,11.372 50.87,11.45 50.87,15.677 62.859,27.666 65.896,27.666 68.4,30.17 68.4,31.613 69.217,32.43 69.386,32.43 69.506,32.31 v1(69.58,32.31)
  Bottom Layer w0.127: v1(69.58,32.31) 69.7,32.43 69.81,32.43 70.08,32.43 70.35,32.16 J18.13@71.05,32.16
MPCIE_CRX_N: J1.85 J18.23 | length 29.9
  Top Layer w0.127: J1.85@51.748,11.368 51.832,11.452 51.832,15.502 63.287,26.957 67.608,26.957 68.507,26.057 68.507,25.077 68.904,24.68 69.473,24.68 69.592,24.8 v1(69.65,24.8)
  Bottom Layer w0.127: v1(69.65,24.8) 69.718,24.8 69.828,24.69 70.08,24.69 70.35,24.96 J18.23@71.05,24.96
MPCIE_CRX_P: J1.83 J18.25 | length 29.5
  Top Layer w0.127: J1.83@52.148,11.372 52.06,11.46 52.06,15.407 63.349,26.696 67.5,26.696 68.247,25.95 68.247,24.969 68.796,24.42 69.473,24.42 69.592,24.3 v1(69.65,24.3)
  Bottom Layer w0.127: v1(69.65,24.3) 69.708,24.3 69.838,24.43 70.08,24.43 70.35,24.16 J18.25@71.05,24.16
MPCIE_CTX_N: J1.79 J18.31 | length 31
  Top Layer w0.127: J1.79@52.948,10.839 52.948,11.368 53.03,11.45 53.03,15.19 63.68,25.84 67.02,25.84 67.363,25.497 67.363,25.129 66.95,24.716 66.95,24.569 67.138,24.38 67.222,24.38 67.342,24.5 v1(67.4,24.5)
  Bottom Layer w0.127: v1(67.4,24.5) 67.458,24.5 67.577,24.38 68.154,24.38 68.58,23.954 68.58,22.148 69.259,21.47 70.06,21.47 70.35,21.76 J18.31@71.05,21.76
MPCIE_CTX_P: J1.77 J18.33 | length 30.1
  Top Layer w0.127: J1.77@53.348,11.372 53.258,11.462 53.258,15.095 63.775,25.612 66.88,25.612 67.103,25.389 67.103,25.237 66.704,24.838 66.689,24.824 66.689,24.461 66.704,24.446 67.03,24.12 67.222,24.12 67.342,24 v1(67.4,24)
  Bottom Layer w0.127: v1(67.4,24) 67.458,24 67.577,24.12 68.046,24.12 68.32,23.846 68.32,22.04 69.151,21.209 70.101,21.209 70.35,20.96 J18.33@71.05,20.96
NetC1_2: C1.2 U4.1 | length 4.9
  Bottom Layer w1.778: C1.2@96.99,64.06 96.99,68.99 U4.1@97,69
NetC8_1: C8.1 R11.2 U6.5 | length 3
  Top Layer w0.1: U6.5@42.95,51.39 43.84,51.39 ; v1(44.05,51.39) 43.84,51.39 ; 43.84,51.39 43.78,51.39 43.84,51.39
  Bottom Layer w0.1: C8.1@42.33,51.34 43.14,51.34 43.39,51.34 43.44,51.39 v1(44.05,51.39)
NetC14_2: C14.2 C15.2 U6.14 | length 4.1
  Top Layer w0.2: U6.14@40,54.39 v1(40,56.01)
  Bottom Layer w0.2: v1(40,56.01) 40.216,55.794 40.38,55.63 C14.2@40.38,54.7 40.393,54.687 C15.2@40.393,53.721
NetC16_2: C16.2 U6.34 | length 3.4
  Top Layer w0.1: U6.34@41,48.39 41,47.73 41.41,47.32 42.59,47.32 C16.2@43.26,46.65
NetC17_2: C17.2 Q3.1 R12.1 U6.33 | length 6.1
  Top Layer w0.127: U6.33@40.5,48.44 40.5,47.426 R12.1@41.444,46.482 41.45,46.476 C17.2@41.45,45.6 41.45,45.13 41.18,44.86 41.18,44.09 41.421,43.849 41.806,44.234 Q3.1@42.121,44.234
NetC18_2: C18.2 Q3.3 R12.2 U6.32 | length 6.6
  Top Layer w0.127: Q3.3@39.921,42.634 40.034,42.634 40.87,43.47 40.87,44.85 40.48,45.24 40.48,45.59 C18.2@40.49,45.6 40.344,45.746 R12.2@40.344,46.482 40.344,46.976 40,47.32 U6.32@40,48.44
NetC20_2: C20.2 J2.64 J6.5 U7.3 | length 56.9
  Top Layer w0.1: v1(52.13,43.67) 52.13,43.587 52.121,43.579 52.34,43.36 52.34,42.791 52.34,42.521 J2.64@52.338,42.519 ; J2.64@52.34,42.23 52.35,42.24 52.35,42.507 v1(52.348,40.594) v1(52.348,40.594) ; U7.3@83.8,43.03 83.79,43.04 v1(83.79,43.97) 84.08,44.26 85.435,44.26 85.75,43.945 85.75,39.833 92.67,32.913 92.67,32.44 93.21,31.9 J6.5@94.3,31.9
  Top Layer w0.161: J2.64@52.338,42.519 J2.64@52.35,42.507
  Int3 (Sign) w0.1: v1(52.348,40.594) 52.348,40.342 52.6,40.09 56.734,40.09 ; 56.734,40.091 79.899,40.091 80.099,40.291 83.778,43.97 v1(83.79,43.97)
  Bottom Layer w0.1: v1@52.12,43.67 52.13,43.68 C20.2@52.13,44.32
NetC21_1: C21.1 R26.1 R28.2 T2.1 | length 5.8
  Top Layer w0.1: R26.1@79.02,28.03 80.01,28.03 80.04,28 80.42,28 80.89,28.47 v1(80.89,29.19)
  Bottom Layer w0.1: R28.2@78.74,30.56 79.15,30.56 79.69,30.02 79.7,30.02 80.04,29.68 T2.1@80.04,29.2 80.88,29.2 v1(80.89,29.19)
NetC24_1: C24.1 D4.2 J4.2 L5.2 | length 16.6
  Top Layer w0.1: v1(35.39,65.33) 35.39,62.27 36.46,61.2 J4.2@37.85,61.2
  Int2 (Sign) w0.1: v1(32.86,64.29) 34.35,64.29 v1(35.39,65.33)
  Bottom Layer w0.1: L5.2@32.86,63.715 v1(32.86,64.29) ; v1(35.39,65.33) 35.99,65.93 35.99,66.73 35.54,67.18 32.29,67.18 C24.1@31.71,66.6 ; C24.1@31.69,66.6 C24.1@31.71,66.6 ; C24.1@31.69,66.6 31.95,66.34 31.97,66.34 C24.1@31.71,66.6 ; C24.1@31.69,66.6 C24.1@31.71,66.6
NetC25_2: C25.2 D3.2 R29.1 T4.1 | length 6
  Top Layer w0.1: v1(79.37,33.09) 80.66,33.09 81.113,33.543 81.113,34.1 C25.2@81.11,34.1 D3.2@81.11,35.12 ; D3.2@81.11,35.295 82.495,35.295 R29.1@82.5,35.29 82.5,35.3 R29.1@82.45,35.35
  Bottom Layer w0.1: v1(79.37,33.09) T4.1@80.355,33.09
NetC26_1: C26.1 J2.18 | length 64
  Top Layer w0.2: J2.18@61.54,42.23 v1(61.54,43.44)
  Int3 (Sign) w0.2: v1(29.73,63.62) 29.26,64.09 29.26,65.326 29.634,65.7 31.16,65.7 32.78,67.32 44.604,67.32 57.556,67.32 59.43,65.446 59.43,56.584 55.91,53.063 55.91,45.694 56.624,44.98 60.604,44.98 61.538,44.046 61.538,43.442 v1(61.54,43.44)
  Bottom Layer w0.2: v1(29.73,63.62) 30.019,63.331 30.019,62.82 C26.1@30.04,62.8
NetC26_2: C26.2 L5.1 R30.1 | length 2.5
  Bottom Layer w0.254: R30.1@31.64,61.49 31.64,62.8 32.855,62.8 L5.1@32.86,62.805
NetC27_1: C27.1 J2.20 | length 60.7
  Top Layer w0.2: v1@61.138,43.74 61.138,42.541 61.14,42.539 J2.20@61.14,42.23
  Int3 (Sign) w0.2: v1(29.8,65.3) 31.184,65.3 32.904,67.02 44.728,67.02 57.432,67.02 59.13,65.322 59.13,56.708 55.61,53.187 55.61,45.57 56.5,44.68 60.338,44.68 v1(61.138,43.88)
  Bottom Layer w0.2: v1(29.8,65.3) 29.95,65.15 C27.1@29.95,64.4
NetC27_2: C27.2 L6.1 R31.2 | length 2.3
  Bottom Layer w0.254: C27.2@31.65,64.4 31.65,65.62 32.763,65.62 32.768,65.615 L6.1@32.77,65.615
NetC28_2: C28.2 D4.1 J4.3 L6.2 | length 13.1
  Top Layer w0.1: v1(34.14,65.62) 34.27,65.75 35.9,65.75 36.45,65.2 J4.3@38.05,65.2
  Bottom Layer w0.1: C28.2@31.64,60.48 32.03,60.48 32.2,60.65 32.2,61.8 32.59,62.19 33.1,62.19 34.14,63.23 v1(34.14,65.62) 34.14,66.48 D4.1@34.09,66.53 34.085,66.525 L6.2@32.77,66.525
NetC29_2: C29.2 J2.10 J11.41 L7.1 | length 112.6
  Top Layer w0.1: J2.10@63.13,42.511 63.138,42.519 63.14,42.517 v1(63.14,43.44)
  Int3 (Sign) w0.1: v1(32.3,67.57) 57.66,67.57 59.68,65.55 59.68,56.48 56.16,52.96 56.16,45.798 56.728,45.23 62.13,45.23 63.14,44.22 v1(63.14,43.44) ; v1(66.5,34.79) 66.77,34.79 67.13,35.15 69.267,35.15 72.01,32.407 72.01,30.11 76.25,25.87 76.25,16.747 76.25,16.708 81.8,11.158 81.8,3.09 J11.41@80.44,1.73
  Bottom Layer w0.1: C29.2@31.65,67.57 v1(32.3,67.57) ; v1(63.14,43.44) 63.14,39.216 63.138,39.214 65.8,36.552 ; 65.8,36.551 66.12,36.231 66.12,35.295 66.12,35.18 66.5,34.8 v1(66.5,34.79)
  Bottom Layer w0.254: C29.2@31.65,67.57 31.65,68.22 31.827,68.397 L7.1@31.9,68.47
NetC30_2: C30.2 J2.2 U9.5 | length 60.4
  Top Layer w0.2: J2.2@64.738,42.519 64.74,42.517 v1(64.74,41.63)
  Int3 (Sign) w0.2: v1(36.07,63.61) 36.07,63.71 38.93,66.57 38.954,66.57 39.104,66.72 57.304,66.72 58.83,65.194 58.83,64.95 58.83,56.832 55.31,53.312 55.31,45.024 56.738,43.596 56.738,43.274 56.972,43.04 57.503,42.51 63.124,42.51 64.004,41.63 v1(64.74,41.63)
  Bottom Layer w0.1: C30.2@36.06,62.85 C30.2@36.07,62.85
  Bottom Layer w0.2: C30.2@36.07,62.85 v1(36.07,63.61)
  Bottom Layer w0.254: C30.2@36.07,62.85 36.07,62.61 36.07,61.48 36.075,61.475 U9.5@36.075,61.46
NetC32_2: C32.2 U9.4 | length 1.5
  Bottom Layer w0.1: C32.2@32.75,61.46 32.79,61.42 34.13,61.42 U9.4@34.17,61.38
NetC33_1: C33.1 U10.3 | length 2.2
  Bottom Layer w0.1: U10.3@39.305,32.93 39.305,32.045 39.86,31.49 C33.1@39.86,30.96
NetC33_2: C33.2 U10.1 | length 2.1
  Bottom Layer w0.1: U10.1@40.605,32.93 40.605,31.925 40.94,31.59 C33.2@40.94,30.96
NetC35_1: C35.1 U10.2 | length 3.1
  Bottom Layer w0.1: U10.2@39.955,32.88 39.955,33.795 40.3,34.14 41.94,34.14 C35.1@41.95,34.15
NetC36_1: C36.1 U10.5 | length 2
  Bottom Layer w0.1: C36.1@37.83,30.97 37.83,31.68 38.005,31.855 U10.5@38.005,32.93
NetC36_2: C36.2 U10.4 | length 2.1
  Bottom Layer w0.1: U10.4@38.655,32.93 38.655,31.875 38.91,31.62 C36.2@38.91,30.97
NetC37_1: C37.1 U10.6 | length 2.1
  Bottom Layer w0.127: C37.1@36.84,30.97 36.84,31.47 37.355,31.985 U10.6@37.355,32.88
NetC38_1: C38.1 U11.4 | length 1.6
  Bottom Layer w0.254: C38.1@37.36,27.9 37.805,27.455 U11.4@37.805,26.44
NetC38_2: C38.2 U11.1 | length 1.6
  Bottom Layer w0.254: U11.1@35.855,26.44 35.855,27.475 C38.2@36.28,27.9
NetC40_1: C40.1 U11.22 | length 2.3
  Bottom Layer w0.1: U11.22@37.155,20.54 37.155,19.745 37.31,19.59 37.87,19.59 38.08,19.38 C40.1@38.08,19
NetC40_2: C40.2 U11.23 | length 1.7
  Bottom Layer w0.1: U11.23@36.505,20.54 36.505,19.495 C40.2@37,19
NetC41_1: C41.1 R33.2 U11.2 | length 4.8
  Top Layer w0.254: v1(38.71,25.33) 38.78,25.33 38.94,25.17 R33.2@38.94,24.71 C41.1@39.85,24.71
  Bottom Layer w0.254: U11.2@36.505,26.44 36.505,25.555 36.73,25.33 v1(38.71,25.33)
NetC42_1: C42.1 U11.24 | length 1.5
  Bottom Layer w0.1: U11.24@35.855,20.54 35.855,19.005 C42.1@35.86,19
NetC43_1: C43.1 U11.21 | length 2.6
  Bottom Layer w0.1: U11.21@37.805,20.54 37.805,20.025 38.22,19.61 38.98,19.61 39.2,19.39 C43.1@39.2,19
NetC44_1: C44.1 R47.2 T5.1 | length 2.3
  Bottom Layer w0.2: C44.1@76.32,40.26 R47.2@77.38,40.26 77.38,39.82 T5.1@76.8,39.24
NetC53_2: C53.2 J16.L9 | length 5.2
  Top Layer w0.305: J16.L9@87.68,57.04 C53.2@92.85,57.04
NetC54_2: C54.2 J16.R9 | length 14.8
  Top Layer w0.254: C54.2@59.73,58.06 61.51,58.06 61.95,58.5 72.25,58.5 J16.R9@73.71,57.04
NetC55_2: C55.2 D6.2 J17.C6 J18.16 | length 29.1
  Top Layer w0.1: v1(51.06,31.95) 51.39,32.28 53.85,32.28 54.69,31.44 61.81,31.44 v1(62.89,30.36)
  Bottom Layer w0.1: C55.2@49.92,31.06 49.92,31.1 D6.2@51.05,31.1 ; J17.C6@50.91,18.52 50.91,19.48 52.33,20.9 52.33,28.607 51.1,29.837 D6.2@51.1,31.1 51.09,31.11 51.06,31.11 v1(51.06,31.95) ; J18.16@62.85,30.96 62.89,30.92 v1(62.89,30.36)
NetC56_2: C56.2 D8.1 J17.C2 J18.14 | length 41.1
  Top Layer w0.1: v1(47.85,32.25) 48.08,32.48 50.685,32.48 ; 50.685,32.48 53.945,32.48 54.785,31.64 62.403,31.64 62.523,31.76 v1(64.2,31.76)
  Bottom Layer w0.1: C56.2@49,31.06 48.96,31.1 D8.1@47.85,31.1 v1(47.85,32.25) 47.85,32.4 48.09,32.64 50.977,32.64 52.25,31.367 52.25,28.97 52.53,28.69 52.53,20.816 51.77,20.056 51.77,17.83 50.91,16.97 J17.C2@50.91,16.72 ; J18.14@62.85,31.76 v1(64.2,31.76)
NetC57_2: C57.2 D7.2 J17.C3 J18.12 | length 29.7
  Top Layer w0.1: v1@55.35,32.175 55.42,32.175 55.755,31.84 62.31,31.84 63.01,32.54 v1(64.2,32.54)
  Bottom Layer w0.1: J17.C3@53.1,16.72 52.55,16.72 52.17,17.1 52.17,19.89 52.94,20.66 52.94,28.82 54.27,30.15 55.05,30.15 55.3,30.4 55.3,31.1 54.2,31.1 C57.2@54.2,31.06 ; D7.2@55.35,31.1 v1(55.35,32.2) ; J18.12@62.85,32.56 62.87,32.54 v1(64.2,32.54)
NetC58_2: C58.2 D7.1 J17.C7 J18.10 R54.2 | length 43.1
  Top Layer w0.1: v1(45.42,31.81) 46.16,31.81 47.03,32.68 50.768,32.68 55.41,32.68 v1(55.89,32.2) 55.934,32.2 56.089,32.045 62.228,32.045 63.463,33.28 v1(64.2,33.28)
  Bottom Layer w0.1: R54.2@43.01,32.09 43.185,31.915 43.185,31.865 43.4,31.65 45.26,31.65 v1(45.42,31.81) ; J17.C7@53.1,18.52 53.1,20.537 53.14,20.577 53.14,28.737 54.353,29.95 56.85,29.95 57.3,30.4 57.3,31.1 C58.2@58.45,31.1 ; v1(55.89,32.2) 56.81,32.2 57.25,31.76 D7.1@57.25,31.1 ; J18.10@62.85,33.36 62.93,33.28 v1(64.2,33.28)
NetC59_2: C59.2 C60.2 D8.2 J17.C1 J18.8 R54.1 | length 41
  Top Layer w0.1: v1(45.95,32.2) 46.26,32.2 46.97,32.91 55.71,32.91 56.375,32.245 62.145,32.245 64.06,34.16 64.15,34.16 v1(64.2,34.21)
  Bottom Layer w0.1: R54.1@42.96,31.04 43.86,31.04 44.77,31.04 45.89,31.04 D8.2@45.95,31.1 ; v1(45.95,32.2) 45.95,31.2 45.9,31.15 D8.2@45.95,31.1 ; J17.C1@48.72,16.72 48.72,16.798 48.27,17.248 47.772,17.248 47.51,17.51 47.51,23.279 47.51,27.2 45.95,28.76 D8.2@45.95,31.1 ; J18.8@62.85,34.16 62.9,34.21 v1(64.2,34.21)
NetC70_2: C70.2 D9.2 L23.2
  other v2: 1.97,31.16 2.57,31.16 3.17,31.16 3.77,31.16 1.37,31.76 1.97,31.76 2.57,31.76 3.17,31.76 3.77,31.76 4.37,31.76 1.37,32.36 1.37,32.96 1.37,33.56 1.37,34.16 1.37,34.76
NetC74_2: C74.2 D10.1 U20.5 | length 3.8
  Top Layer w0.2: C74.2@25.04,51.78 25.16,51.78 26.24,50.7 U20.5@26.24,49.99 26.24,49.32 26.46,49.1 D10.1@26.46,48.62
NetC81_2: C81.2 U22.2 | length 1.5
  Top Layer w0.1: U22.2@20.5,47.385 21.165,47.385 21.31,47.24 C81.2@21.91,47.24
NetC84_2: C84.2 R75.1 | length 1
  Top Layer w0.254: R75.1@23.05,46.2 C84.2@24.01,46.2
NetC85_1: C85.1 R84.1 R85.2 U23.4 | length 3.1
  Bottom Layer w0.305: U23.4@75.7,15.9 75.7,17.22 75.725,17.195 76.545,17.195 76.615,17.265 76.615,17.983 76.63,17.998 C85.1@76.63,18.1
NetC89_1: C89.1 R87.1 R88.2 U24.4 | length 3
  Top Layer w0.2: U24.4@14.72,26.72 16.01,26.72 R88.2@16.02,26.71 R87.1@16.02,27.52 16.94,27.52 C89.1@16.95,27.53
NetC102_1: C102.1 U29.D4 | length 1
  Top Layer w0.2: U29.D4@29.09,58.82 C102.1@29.09,59.81
NetC103_2: C103.2 U30.4 | length 1.6
  Bottom Layer w0.2: U30.4@33.83,55.96 33.83,57.1 C103.2@34.16,57.43
NetD1_1: D1.1 J2.42 Q2.1 U20.1 | length 76.6
  Top Layer w0.1: Q2.1@14.02,25.585 14.02,26.358 14.02,27.65 v1(14.03,27.66) ; v1(27.5,48.04) 27.5,49.42 28.07,49.99 U20.1@28.84,49.99 29.14,49.99 29.65,49.48 30.5,49.48 30.91,49.07 v1(30.91,48.95) ; v1(55.91,40.85) 56.485,40.85 56.555,40.92 56.56,40.92 56.738,41.098 J2.42@56.738,42.519
  Int2 (Sign) w0.1: v1(30.91,48.95) 31.157,48.95 38.807,41.3 38.834,41.3 38.844,41.29 52.1,41.29 52.86,41.29 53.15,41 53.241,40.909 53.862,40.909 53.993,41.04 55.72,41.04 v1(55.91,40.85)
  Int3 (Sign) w0.1: v1(8.73,27.4) 9.09,27.76 11.854,27.76 11.954,27.66 v1(14.03,27.66) 14.23,27.46 19.82,27.46 20.75,28.39 20.75,41.387 21.943,42.58 23.917,42.58 25.85,44.513 25.85,46.39 v1(27.5,48.04)
  Bottom Layer w0.1: D1.1@7.12,26.825 8.155,26.825 v1(8.73,27.4)
NetD1_3: D1.3 J20.10 R6.1 | length 5.7
  Top Layer w0.1: J20.10@2.72,29.56 v1(4.25,29.56)
  Bottom Layer w0.1: v1(4.25,29.56) 4.466,29.344 4.835,28.975 D1.3@6.47,28.975 6.475,28.98 R6.1@8.21,28.98
NetD3_3: D3.3 J2.56 | length 29.8
  Top Layer w0.1: J2.56@53.938,42.519 53.938,40.84 54.24,40.538 54.445,40.333 56.218,38.56 v1(56.88,38.56) ; v1(79.713,37.583) 80.447,37.583 D3.3@80.46,37.57
  Int3 (Sign) w0.1: v1(56.88,38.56) 57.667,38.56 57.997,38.89 78.4,38.89 79.707,37.583 v1(79.713,37.583)
NetD5_1: D5.1 J4.1 L7.2 | length 22.6
  Top Layer w0.2: v1(30.27,68.47) 30.27,63.14 31.05,62.36 J4.1@31.05,59.7
  Int2 (Sign) w0.3: v1(30.27,68.47) 30.46,68.66 37.18,68.66 39.53,66.31 v1(39.53,65.24)
  Bottom Layer w0.2: v1(30.27,68.47) L7.2@30.845,68.47
  Bottom Layer w0.3: D5.1@38.95,66.51 38.95,65.82 v1(39.53,65.24)
NetD10_3: D10.3 R62.1 R69.2 T10.2 | length 82.1
  Top Layer w0.1: v1(10.38,65.85) R69.2@10.38,66.46 ; T10.2@15.3,5.5 15.3,7.61 15.975,8.285 15.975,21.335 20.23,25.59 v1(20.23,30.44) ; v1(25.5,46.25) 26.07,46.82 26.88,46.82 27.55,47.49 ; v1(27.07,52.64) 27.07,47.97 27.55,47.49 ; R62.1@30.04,48.93 30.04,48.35 29.66,47.97 D10.3@28.61,47.97 28.03,47.97 27.55,47.49
  Int2 (Sign) w0.1: v1@10.27,65.85 12.487,65.85 17.03,61.307 17.03,59.415 17.03,59.125 17.03,58.384 22.624,52.79 26.332,52.79 26.482,52.64 v1(27.07,52.64)
  Int3 (Sign) w0.1: v1(20.23,30.44) 20.23,30.46 20.55,30.78 20.55,41.47 21.86,42.78 23.834,42.78 25.5,44.446 v1(25.5,46.25)
NetD11_3: D11.3 D12.3 R76.1 | length 6.8
  Bottom Layer w0.305: D12.3@49.42,39.535 52.83,39.535 D11.3@52.85,39.515 53.215,39.515 54.59,38.14 R76.1@55.69,38.14
NetD12_1: D12.1 R78.1 | length 1.4
  Bottom Layer w0.305: D12.1@50.07,37.385 50.07,36.6 R78.1@50.54,36.13
NetD13_2: D13.2 R80.1 | length 1.5
  Top Layer w0.1: D13.2@15.4,69.25 v1(15.4,70)
  Bottom Layer w0.1: R80.1@15.4,69.25 v1(15.4,70)
NetD14_2: D14.2 R81.1 | length 1.5
  Top Layer w0.1: D14.2@16.8,69.25 v1(16.8,70)
  Bottom Layer w0.1: R81.1@16.8,69.25 v1(16.8,70)
NetD15_2: D15.2 R82.1 | length 1.5
  Top Layer w0.1: D15.2@14,69.25 v1(14,70)
  Bottom Layer w0.1: R82.1@14,69.25 v1(14,70)
NetJ1_2: J1.2 J15.4 | length 65.2
  Top Layer w0.1: J1.2@68.55,8.19 68.55,8.501 68.55,8.85 v1(68.75,9.05) ; J15.4@93.49,47.895 94.765,47.895 v1(94.77,47.9)
  Int2 (Sign) w0.1: v1(68.75,9.05) 69.85,10.15 88.68,10.15 94.827,16.297 94.827,20.957 97.09,23.22 97.09,46.32 95.51,47.9 v1(94.77,47.9)
NetJ1_4: J1.4 J11.16 | length 27.4
  Top Layer w0.1: J1.4@68.15,8.231 68.15,8.501 68.15,8.945 68.401,9.196 68.401,9.756 v1(68.399,9.758)
  Int3 (Sign) w0.1: J11.16@47.42,4.27 48.07,3.62 48.58,3.11 55.917,3.11 56.18,3.373 56.18,4.94 57.39,6.15 61.239,6.15 62.26,7.171 63.019,7.93 67.72,7.93 68.399,8.609 v1(68.399,9.758)
NetJ1_6: J1.6 J11.17 | length 27
  Top Layer w0.1: J1.6@67.748,8.229 67.748,9.098 68.046,9.396 v1(68.046,9.404)
  Int3 (Sign) w0.1: J11.17@49.96,1.73 51.13,2.9 55.99,2.9 56.38,3.29 56.38,4.857 57.473,5.95 61.321,5.95 63.101,7.73 67.925,7.73 68.895,8.7 69.11,8.915 69.11,9.81 68.812,10.108 68.254,10.108 68.046,9.899 v1(68.046,9.404)
NetJ1_7: J1.7 J13.28 | length 33.3
  Top Layer w0.1: J1.7@67.348,10.839 67.348,10.252 v1(67.65,9.95)
  Int2 (Sign) w0.1: v1(67.65,9.95) 68.065,10.365 85.344,10.365 85.619,10.64 ; 85.62,10.64 86.77,11.79 v1(87,11.79)
  Int3 (Sign) w0.1: v1(87,11.79) 87.81,10.98 93.53,10.98 96.06,13.51 v1(96.06,14)
  Bottom Layer w0.1: J13.28@94.86,14 v1(96.06,14)
NetJ1_9: J1.9 J14.2 | length 76.1
  Top Layer w0.1: J1.9@66.948,10.839 66.95,10.837 66.95,10.04 v1(66.95,10.08) ; J14.2@93.59,60.855 93.595,60.85 v1(94.99,60.85)
  Int2 (Sign) w0.1: v1(66.95,10.08) 67.44,10.57 85.266,10.57 90.656,15.96 91.806,15.96 92.71,16.864 92.71,17.804 92.71,40.796 92.71,41.812 92.71,42.268 92.71,45.4 93.82,46.51 93.82,57.87 95.4,59.45 95.4,60.44 v1(94.99,60.85)
NetJ1_10: J1.10 J11.24 U18.4 | length 86.9
  Top Layer w0.1: J11.24@57.58,4.27 58.69,3.16 60.96,3.16 61.15,3.35 61.15,5.01 62.14,6 65.77,6 66.95,7.18 J1.10@66.95,7.94 v1@66.95,9.42
  Int3 (Sign) w0.1: v1(5.26,12.84) 7.03,11.07 7.03,8.611 7.26,8.38 7.42,8.38 10.46,5.34 31.433,5.34 31.663,5.57 36.013,5.57 36.723,6.28 40.74,6.28 55.155,6.28 56.19,7.315 56.19,9.285 56.883,9.978 60.494,9.978 61.012,9.46 61.495,9.46 61.89,9.46 62.18,9.17 62.18,8.936 62.976,8.14 66.122,8.14 66.9,8.918 66.9,9.22 66.901,9.221 66.901,9.381 v1(66.95,9.43)
  Bottom Layer w0.1: U18.4@4.045,12.835 4.05,12.84 v1(5.26,12.84)
NetJ1_11: J1.11 J14.3 | length 75.5
  Top Layer w0.1: J1.11@66.548,10.839 66.55,10.837 66.55,9.72 v1(66.55,9.75) ; J14.3@93.59,59.605 93.595,59.6 v1(94.99,59.6) v1@95.05,59.6
  Int2 (Sign) w0.1: v1(66.55,9.75) 66.55,10.175 67.145,10.77 85.183,10.77 90.573,16.16 91.723,16.16 92.51,16.947 92.51,17.887 92.51,40.713 92.51,41.895 92.51,42.185 92.51,45.483 93.62,46.593 93.62,58.23 v1(94.99,59.6)
NetJ1_12: J1.12 J11.26 U18.1 | length 78
  Top Layer w0.1: J11.26@60.12,4.27 62.062,6.211 65.699,6.211 66.55,7.063 J1.12@66.55,7.94 v1(66.55,9.063) v1@66.55,9.1
  Int2 (Sign) w0.1: v1@66.55,9.1 v1@66.56,9.09
  Int3 (Sign) w0.1: v1(7.405,8.73) 7.405,8.678 10.543,5.54 31.35,5.54 31.58,5.77 35.93,5.77 36.64,6.48 55.072,6.48 55.99,7.398 55.99,9.368 56.8,10.178 60.577,10.178 60.88,9.875 61.095,9.66 61.578,9.66 62,9.66 62.38,9.28 62.38,9.019 63.05,8.349 66.029,8.349 66.518,8.838 66.518,9.031 v1(66.55,9.063)
  Bottom Layer w0.1: U18.1@4.045,9.025 5.585,9.025 5.88,8.73 v1(7.405,8.73)
NetJ1_13: J1.13 J14.1 R48.1 | length 89.1
  Top Layer w0.1: J14.1@93.506,62.021 93.59,62.105 94.975,62.105 v1(94.99,62.09)
  Top Layer w0.127: J1.13@66.148,10.839 66.15,10.837 v1(66.15,10.07)
  Int2 (Sign) w0.1: v1(66.15,10.07) 66.15,10.088 67.032,10.97 85.1,10.97 90.49,16.36 91.64,16.36 92.31,17.03 92.31,40.63 92.31,41.868 92.16,42.018 v1(92.16,42.04) 92.16,42.102 92.28,42.222 92.28,45.54 93.42,46.68 93.42,60.52 v1(94.99,62.09)
  Int3 (Sign) w0.1: v1(82.69,39.83) 89.95,39.83 v1(92.16,42.04)
  Bottom Layer w0.1: R48.1@81.57,39.83 v1(82.69,39.83)
NetJ1_14: J1.14 J11.36 | length 14.2
  Top Layer w0.1: v1(66.13,9.43) 66.14,9.42 66.14,8.17 J1.14@66.15,8.16
  Int3 (Sign) w0.1: J11.36@72.62,4.47 J11.36@72.82,4.27 72.82,8.06 72.62,8.26 72.62,8.68 72.96,9.02 v1(72.96,9.06)
  Bottom Layer w0.1: v1(66.13,9.43) 66.13,8.956 66.436,8.65 72.55,8.65 v1(72.96,9.06)
NetJ1_16: J1.16 J11.38 | length 13.7
  Top Layer w0.1: v1(65.74,9.063) 65.745,9.058 65.745,8.165 J1.16@65.75,8.16
  Int3 (Sign) w0.1: v1(72.97,8.53) 75.36,6.14 J11.38@75.36,4.27
  Bottom Layer w0.1: v1(65.74,9.063) 66.253,8.55 66.353,8.45 72.633,8.45 72.733,8.55 72.95,8.55 v1(72.97,8.53)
